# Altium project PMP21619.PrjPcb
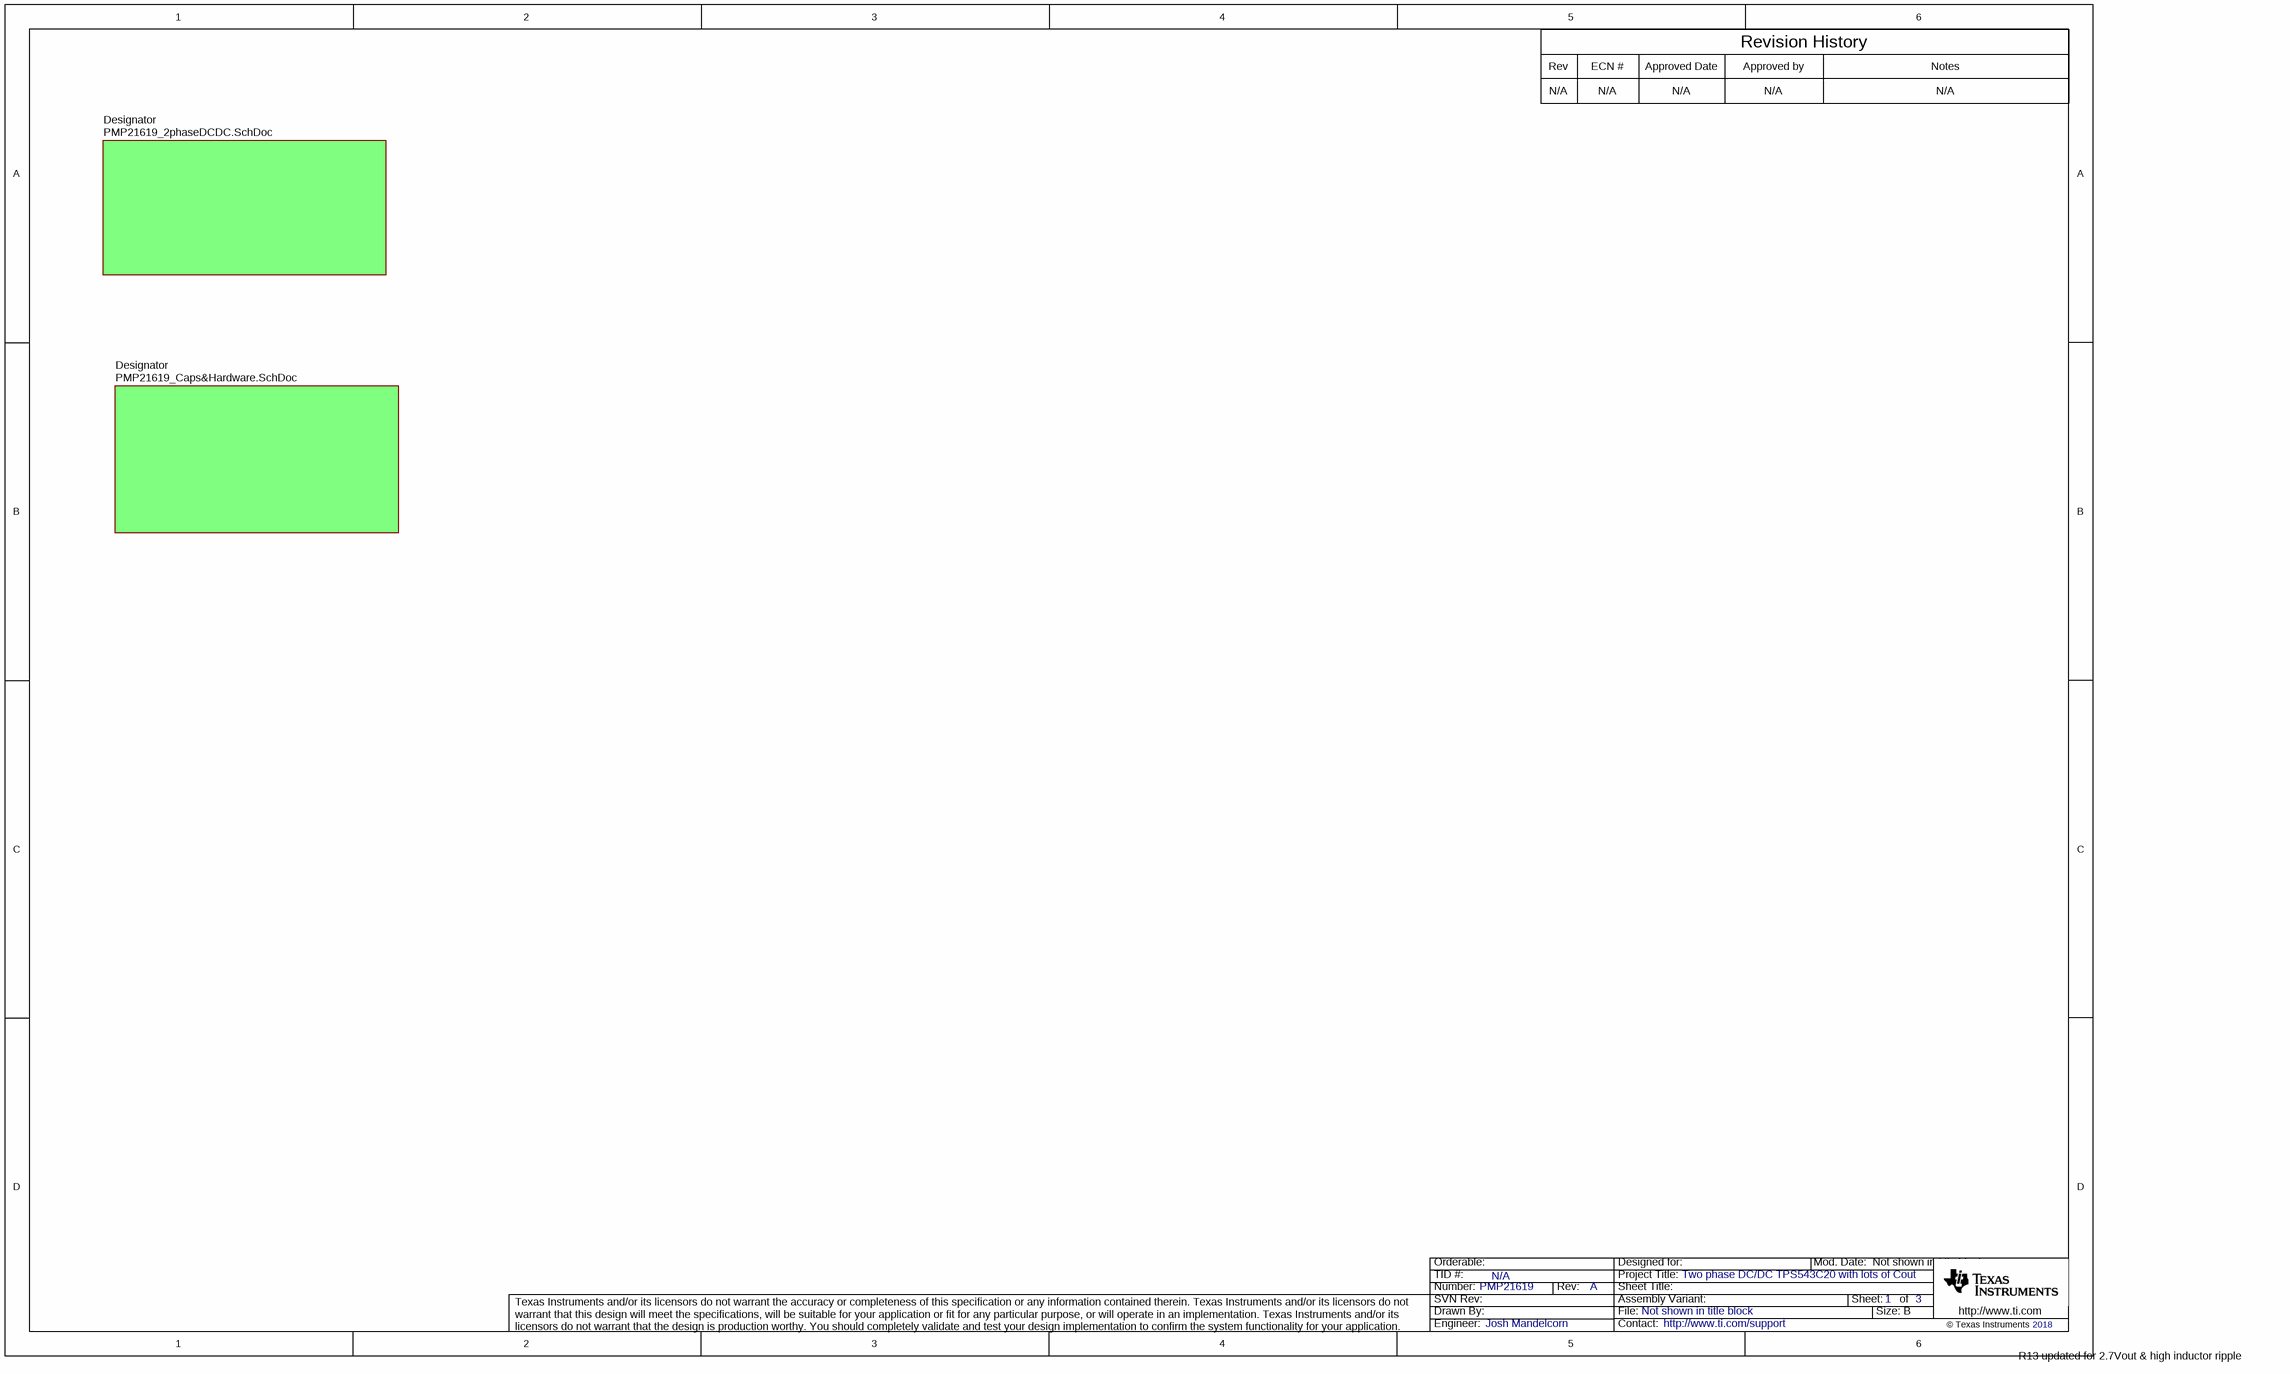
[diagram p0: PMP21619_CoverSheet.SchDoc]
CopyrightYear: 2018; PCB_Layout: Dee Lim; PCB_Rev: A; PRJ_Engineer: Josh Mandelcorn; PRJ_Number: PMP21619; PRJ_Title: Two phase DC/DC TPS543C20 with lots of Cout; SCH_Rev: A; TechSupport: http://www.ti.com/support; TID: N/A
3 sheets, 231 parts. Net scope: flat (ports and power ports of the same name join across sheets).
Board file: PMP21619_PCB.PcbDoc
Sheets:
  PMP21619_CoverSheet.SchDoc
    Designator = PMP21619_2phaseDCDC.SchDoc
    Designator = PMP21619_Caps&Hardware.SchDoc

## Sheet PMP21619_CoverSheet.SchDoc
size 431 x 279 mm; Date: Not shown in title block; ApprovedBy: Not shown in title block; CheckedBy: Not shown in title block; Author: Not shown in title block; CompanyName: Not shown in title block; Engineer: Not shown in title block; Organization: Not shown in title block; Address1: Not shown in title block; Address2: Not shown in title block; Address3: Not shown in title block; Address4: Not shown in title block; DocumentNumber: 1; Revision: Use project parameter SCH_Rev; SheetNumber: 1; SheetTotal: 3; PageSetup: Record=PageOptions¦CenterHorizontal=True¦CenterVertical=True¦PrintScale=1.00¦XCorrection=1.00¦YCorrection=1.00¦PrintKind=0¦BorderSize=5000000¦LeftOffset=0¦BottomOffset=0¦Orientation=2¦PaperLength=1000¦PaperWidth=1000¦Scale=100¦PaperSource=15¦PrintQuality=600¦MediaType=1¦DitherType=10¦PaperKind=Letter¦PrintScaleMode=1

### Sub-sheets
Designator = PMP21619_2phaseDCDC.SchDoc: no entries
Designator = PMP21619_Caps&Hardware.SchDoc: no entries

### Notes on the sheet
- Rev
- N/A
- ECN #
- Approved Date
- Approved by
- Revision History
- Notes
- R13 updated for 2.7Vout & high inductor ripple

## Sheet PMP21619_2phaseDCDC.SchDoc
size 431 x 279 mm; Date: Not shown in title block; ApprovedBy: Not shown in title block; CheckedBy: Not shown in title block; Author: Not shown in title block; CompanyName: Not shown in title block; Engineer: Not shown in title block; Organization: Not shown in title block; Address1: Not shown in title block; Address2: Not shown in title block; Address3: Not shown in title block; Address4: Not shown in title block; DocumentNumber: 1; Revision: Use project parameter SCH_Rev; SheetNumber: 2; SheetTotal: 3; PageSetup: Record=PageOptions¦CenterHorizontal=True¦CenterVertical=True¦PrintScale=1.00¦XCorrection=1.00¦YCorrection=1.00¦PrintKind=0¦BorderSize=5000000¦LeftOffset=0¦BottomOffset=0¦Orientation=2¦PaperLength=1000¦PaperWidth=1000¦Scale=100¦PaperSource=15¦PrintQuality=600¦MediaType=1¦DitherType=10¦PaperKind=Letter¦PrintScaleMode=1
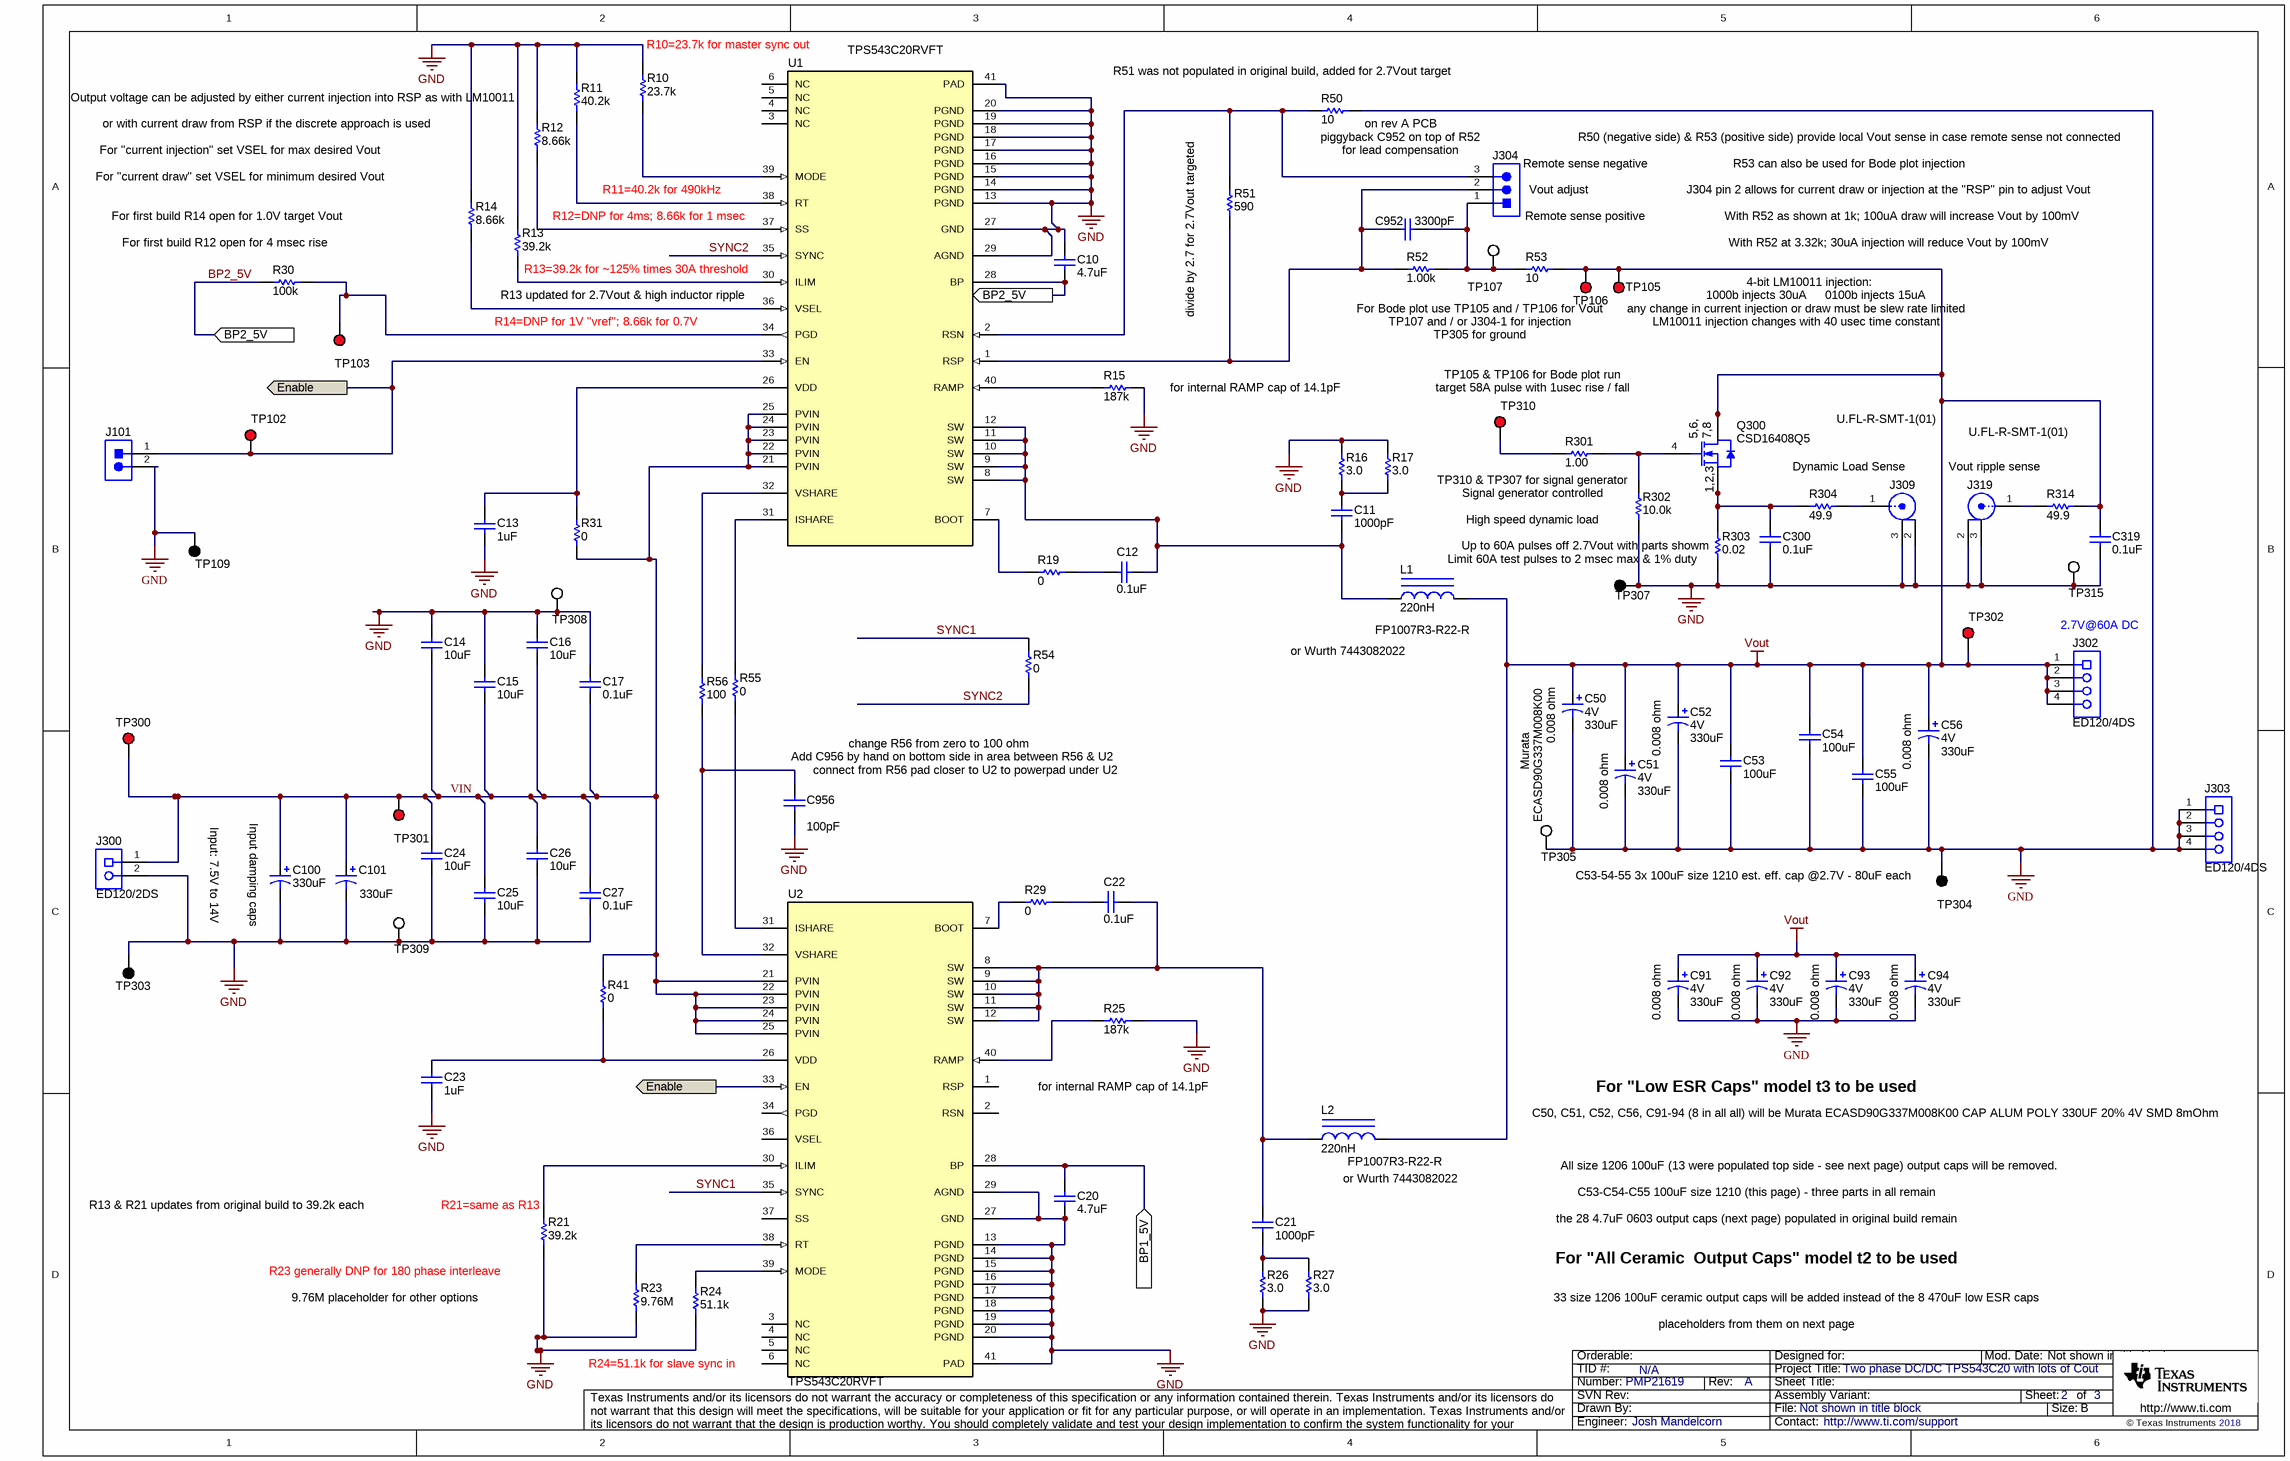
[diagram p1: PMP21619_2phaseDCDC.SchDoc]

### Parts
C10  ValueDisplayed: 4.7uF  [0805_HV]  (hidden comment: Capacitor)
C11  ValueDisplayed: 1000pF  [0603]  (hidden comment: Capacitor)
C12  ValueDisplayed: 0.1uF  [0402]  (hidden comment: Capacitor)
C13  ValueDisplayed: 1uF  [0603]  (hidden comment: Capacitor)
C14  ValueDisplayed: 10uF  [1210_280]  (hidden comment: Capacitor)
C15  ValueDisplayed: 10uF  [1210_280]  (hidden comment: Capacitor)
C16  ValueDisplayed: 10uF  [1210_280]  (hidden comment: Capacitor)
C17  ValueDisplayed: 0.1uF  [0603S]  (hidden comment: Capacitor)
C20  ValueDisplayed: 4.7uF  [0805_HV]  (hidden comment: Capacitor)
C21  ValueDisplayed: 1000pF  [0603]  (hidden comment: Capacitor)
C22  ValueDisplayed: 0.1uF  [0402]  (hidden comment: Capacitor)
C23  ValueDisplayed: 1uF  [0603]  (hidden comment: Capacitor)
C24  ValueDisplayed: 10uF  [1210_280]  (hidden comment: Capacitor)
C25  ValueDisplayed: 10uF  [1210_280]  (hidden comment: Capacitor)
C26  ValueDisplayed: 10uF  [1210_280]  (hidden comment: Capacitor)
C27  ValueDisplayed: 0.1uF  [0603S]  (hidden comment: Capacitor)
C50  ECASD90G337M008K00  Value1: 0.008 ohm  Manufacturer: Murata  VDC_V: 4V  ValueDisplayed: 330uF  [CAPSMT_62_H70]
C51  Value1: 0.008 ohm  VDC_V: 4V  ValueDisplayed: 330uF  [CAPSMT_62_H70]  (hidden comment: ECASD90G337M008K00)
C52  Value1: 0.008 ohm  VDC_V: 4V  ValueDisplayed: 330uF  [CAPSMT_62_H70]  (hidden comment: ECASD90G337M008K00)
C53  ValueDisplayed: 100uF  [1210_280]  (hidden comment: Capacitor)
C54  ValueDisplayed: 100uF  [1210_280]  (hidden comment: Capacitor)
C55  ValueDisplayed: 100uF  [1210_280]  (hidden comment: Capacitor)
C56  Value1: 0.008 ohm  VDC_V: 4V  ValueDisplayed: 330uF  [CAPSMT_62_H70]  (hidden comment: ECASD90G337M008K00)
C91  Value1: 0.008 ohm  VDC_V: 4V  ValueDisplayed: 330uF  [CAPSMT_62_H70]  (hidden comment: ECASD90G337M008K00)
C92  Value1: 0.008 ohm  VDC_V: 4V  ValueDisplayed: 330uF  [CAPSMT_62_H70]  (hidden comment: ECASD90G337M008K00)
C93  Value1: 0.008 ohm  VDC_V: 4V  ValueDisplayed: 330uF  [CAPSMT_62_H70]  (hidden comment: ECASD90G337M008K00)
C94  Value1: 0.008 ohm  VDC_V: 4V  ValueDisplayed: 330uF  [CAPSMT_62_H70]  (hidden comment: ECASD90G337M008K00)
C100  value 330uF  [SM_RADIAL_G]  (hidden comment: Cap_Polarized)
C101  value 330uF  [SM_RADIAL_G]  (hidden comment: Cap_Polarized)
C300  ValueDisplayed: 0.1uF  [0603]  (hidden comment: Capacitor)
C319  ValueDisplayed: 0.1uF  [0603]  (hidden comment: Capacitor)
C952  ValueDisplayed: 3300pF  [0402]  (hidden comment: GCM155R71H332KA37D)
C956  ValueDisplayed: 100pF  [0402]  (hidden comment: 0402YC101KAT2A)
J101  Header_2x1  [Mill-Max_800-10-002-10-001000]  (value not drawn)
J300  ED120/2DS  [On-Shore_ED120_2DS]
J302  ED120/4DS  [On-Shore_ED120_4DS]
J303  ED120/4DS  [On-Shore_ED120_4DS]
J304  800-10-003-10-001000  [Mill-Max_800-10-003-10-001000]  (value not drawn)
J309  U.FL-R-SMT-1(01)  [CONN_UFL-R-SMT-1]
J319  U.FL-R-SMT-1(01)  [CONN_UFL-R-SMT-1]
L1  FP1007R3-R22-R  ValueDisplayed: 220nH  [IND_FP1007R3]
L2  FP1007R3-R22-R  ValueDisplayed: 220nH  [IND_FP1007R3]
Q300  CSD16408Q5  [DQH0008A]
R10  ValueDisplayed: 23.7k  [0402]  (hidden comment: Resistor)
R11  ValueDisplayed: 40.2k  [0402]  (hidden comment: Resistor)
R12  ValueDisplayed: 8.66k  [0402]  (hidden comment: Resistor)
R13  ValueDisplayed: 39.2k  [0402]  (hidden comment: CRCW040239K2FKED)
R14  ValueDisplayed: 8.66k  [0402]  (hidden comment: Resistor)
R15  ValueDisplayed: 187k  [0402]  (hidden comment: Resistor)
R16  value 3.0  [0805_HV]  (hidden comment: Resistor)
R17  value 3.0  [0805_HV]  (hidden comment: Resistor)
R19  ValueDisplayed: 0  [0402]  (hidden comment: Resistor)
R21  ValueDisplayed: 39.2k  [0402]  (hidden comment: CRCW040239K2FKED)
R23  ValueDisplayed: 9.76M  [0402]  (hidden comment: CRCW04029M76FKED)
R24  ValueDisplayed: 51.1k  [0402]  (hidden comment: Resistor)
R25  ValueDisplayed: 187k  [0402]  (hidden comment: Resistor)
R26  value 3.0  [0805_HV]  (hidden comment: Resistor)
R27  value 3.0  [0805_HV]  (hidden comment: Resistor)
R29  ValueDisplayed: 0  [0402]  (hidden comment: Resistor)
R30  ValueDisplayed: 100k  [0402]  (hidden comment: Resistor)
R31  ValueDisplayed: 0  [0402]  (hidden comment: Resistor)
R41  ValueDisplayed: 0  [0402]  (hidden comment: Resistor)
R50  ValueDisplayed: 10  [0402]  (hidden comment: Resistor)
R51  ValueDisplayed: 590  [0402]  (hidden comment: CRCW0402590RFKED)
R52  ValueDisplayed: 1.00k  [0402]  (hidden comment: Resistor)
R53  ValueDisplayed: 10  [0402]  (hidden comment: Resistor)
R54  ValueDisplayed: 0  [0402]  (hidden comment: Resistor)
R55  ValueDisplayed: 0  [0402]  (hidden comment: Resistor)
R56  ValueDisplayed: 100  [0402]  (hidden comment: ERJ-2RKF1000X)
R301  ValueDisplayed: 1.00  [0603]  (hidden comment: Resistor)
R302  ValueDisplayed: 10.0k  [0603]  (hidden comment: Resistor)
R303  ValueDisplayed: 0.02  [2512]  (hidden comment: Resistor)
R304  ValueDisplayed: 49.9  [0402]  (hidden comment: Resistor)
R314  ValueDisplayed: 49.9  [0402]  (hidden comment: Resistor)
TP102  5000  [Keystone5000]  (value not drawn)
TP103  5000  [Keystone5000]  (value not drawn)
TP105  5000  [Keystone5000]  (value not drawn)
TP106  5000  [Keystone5000]  (value not drawn)
TP107  5002  [Keystone5002]  (value not drawn)
TP109  5001  [Keystone5001]  (value not drawn)
TP300  5000  [Keystone5000]  (value not drawn)
TP301  5000  [Keystone5000]  (value not drawn)
TP302  5000  [Keystone5000]  (value not drawn)
TP303  5001  [Keystone5001]  (value not drawn)
TP304  5001  [Keystone5001]  (value not drawn)
TP305  5016  [Testpoint_Keystone_Compact]  (value not drawn)
TP307  5001  [Keystone5001]  (value not drawn)
TP308  5016  [Testpoint_Keystone_Compact]  (value not drawn)
TP309  5016  [Testpoint_Keystone_Compact]  (value not drawn)
TP310  5000  [Keystone5000]  (value not drawn)
TP315  5016  [Testpoint_Keystone_Compact]  (value not drawn)
U1  PartNumber: TPS543C20RVFT  [RVF0040A]
U2  TPS543C20RVFT  [RVF0040A]

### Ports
BP1_5V, BP2_5V, Enable

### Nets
GND: C10.1 C13.2 C14.1 C15.1 C16.1 C17.1 C20.2 C23.2 C24.2 C25.2 C26.2 C27.2 C50.2(-) C51.2(-) C52.2(-) C53.2 C54.2 C55.2 C56.2(-) C91.2(-) C92.2(-) C93.2(-) C94.2(-) C100.2(-) C101.2(-) C300.2 C319.2 C956.2 J101.2 J300.2 J303.1 J303.2 J303.3 J303.4 J309.2 J309.3 J319.2 J319.3 R10.1 R11.1 R12.1 R13.2 R14.2 R15.2 R16.1 R17.1 R21.1 R23.1 R24.1 R25.2 R26.1 R27.2 R50.1 R302.1 R303.1 TP109.1 TP303.1 TP304.1 TP305.1 TP307.1 TP308.1 TP309.1 TP315.1 U1.13(PGND) U1.14(PGND) U1.15(PGND) U1.16(PGND) U1.17(PGND) U1.18(PGND) U1.19(PGND) U1.20(PGND) U1.27(GND) U1.29(AGND) U1.41(PAD) U2.13(PGND) U2.14(PGND) U2.15(PGND) U2.16(PGND) U2.17(PGND) U2.18(PGND) U2.19(PGND) U2.20(PGND) U2.27(GND) U2.29(AGND) U2.41(PAD)
Vout: C50.1(+) C51.1(+) C52.1(+) C53.1 C54.1 C55.1 C56.1(+) C91.1(+) C92.1(+) C93.1(+) C94.1(+) C319.1 J302.1 J302.2 J302.3 J302.4 L1.2 L2.2 Q300.5(D) Q300.6(D) Q300.7(D) Q300.8(D) Q300.9(D) R53.1 R314.2 TP105.1 TP106.1 TP302.1
BP1_5V: C20.1 U2.28(BP) ; port BP1_5V
BP2_5V: C10.2 R30.1 U1.28(BP) ; port BP2_5V
Enable: J101.1 TP102.1 U1.33(EN) U2.33(EN) ; port Enable
SYNC1: R54.2 U2.35(SYNC)
SYNC2: R54.1 U1.35(SYNC)
VIN: C14.2 C15.2 C16.2 C17.2 C24.1 C25.1 C26.1 C27.1 C100.1(+) C101.1(+) J300.1 R31.1 R41.2 TP300.1 TP301.1 U1.21(PVIN) U1.22(PVIN) U1.23(PVIN) U1.24(PVIN) U1.25(PVIN) U2.21(PVIN) U2.22(PVIN) U2.23(PVIN) U2.24(PVIN) U2.25(PVIN)
NetC11_1: C11.1 C12.2 L1.1 U1.8(SW) U1.9(SW) U1.10(SW) U1.11(SW) U1.12(SW)
NetC11_2: C11.2 R16.2 R17.2
NetC12_1: C12.1 R19.1
NetC13_1: C13.1 R31.2 U1.26(VDD)
NetC21_1: C21.1 C22.2 L2.1 U2.8(SW) U2.9(SW) U2.10(SW) U2.11(SW) U2.12(SW)
NetC21_2: C21.2 R26.2 R27.1
NetC22_1: C22.1 R29.1
NetC23_1: C23.1 R41.1 U2.26(VDD)
NetC300_1: C300.1 Q300.1(S) Q300.2(S) Q300.3(S) R303.2 R304.1
NetC952_1: C952.1 J304.2 R51.1 R52.2 U1.1(RSP)
NetC952_2: C952.2 J304.1 R52.1 R53.2 TP107.1
NetC956_1: C956.1 R56.1 U2.32(VSHARE)
NetJ304_3: J304.3 R50.2 R51.2 U1.2(RSN)
NetJ309_1: J309.1 R304.2
NetJ319_1: J319.1 R314.1
NetQ300_4: Q300.4(G) R301.1 R302.2
NetR10_2: R10.2 U1.39(MODE)
NetR11_2: R11.2 U1.38(RT)
NetR12_2: R12.2 U1.37(SS)
NetR13_1: R13.1 U1.30(ILIM)
NetR14_1: R14.1 U1.36(VSEL)
NetR15_1: R15.1 U1.40(RAMP)
NetR19_2: R19.2 U1.7(BOOT)
NetR21_2: R21.2 U2.30(ILIM)
NetR23_2: R23.2 U2.38(RT)
NetR24_2: R24.2 U2.39(MODE)
NetR25_1: R25.1 U2.40(RAMP)
NetR29_2: R29.2 U2.7(BOOT)
NetR30_2: R30.2 TP103.1 U1.34(PGD)
NetR55_1: R55.1 U2.31(ISHARE)
NetR55_2: R55.2 U1.31(ISHARE)
NetR56_2: R56.2 U1.32(VSHARE)
NetR301_2: R301.2 TP310.1

Not connected (* = marked no-connect by the designer): U1 3(NC) 4(NC) 5(NC) 6(NC); U2 1(RSP) 2(RSN) 3(NC) 4(NC) 5(NC) 6(NC) 34(PGD) 36(VSEL) 37(SS)

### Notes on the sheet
- (near R12) Output voltage can be adjusted by either current injection into RSP as with LM10011
- R10=23.7k for master sync out
- (near R50) R51 was not populated in original build, added for 2.7Vout target
- For "current injection" set VSEL for max desired Vout
- or with current draw from RSP if the discrete approach is used
- (near R50) on rev A PCB
- (near R50) piggyback C952 on top of R52
- for lead compensation
- (near J304) Remote sense negative
- R50 (negative side) & R53 (positive side) provide local Vout sense in case remote sense not connected
- R53 can also be used for Bode plot injection
- For first build R14 open for 1.0V target Vout
- For "current draw" set VSEL for minimum desired Vout
- R12=DNP for 4ms; 8.66k for 1 msec
- R11=40.2k for 490kHz
- (near R51) divide by 2.7 for 2.7Vout targeted
- (near J304) Vout adjust
- Remote sense positive
- J304 pin 2 allows for current draw or injection at the "RSP" pin to adjust Vout
- With R52 as shown at 1k; 100uA draw will increase Vout by 100mV
- (near R30) For first build R12 open for 4 msec rise
- R13 updated for 2.7Vout & high inductor ripple
- (near R13) R13=39.2k for
  25% times 30A threshold
- 1000b injects 30uA
- 4-bit LM10011 injection:
- 0100b injects 15uA
- With R52 at 3.32k; 30uA injection will reduce Vout by 100mV
- R14=DNP for 1V "vref"; 8.66k for 0.7V
- For Bode plot use TP105 and / TP106 for Vout
- TP107 and / or J304-1 for injection
- TP305 for ground
- any change in current injection or draw must be slew rate limited
- (near TP105) LM10011 injection changes with 40 usec time constant
- (near R15) for internal RAMP cap of 14.1pF
- TP105 & TP106 for Bode plot run
- (near TP310) target 58A pulse with 1usec rise / fall
- Signal generator controlled
- (near R302) TP310 & TP307 for signal generator
- Dynamic Load Sense
- Vout ripple sense
- High speed dynamic load
- Limit 60A test pulses to 2 msec max & 1% duty
- (near R303) Up to 60A pulses off 2.7Vout with parts showm
- 2.7V@60A DC
- (near L1) or Wurth 7443082022
- change R56 from zero to 100 ohm
- (near C956) Add C956 by hand on bottom side in area between R56 & U2
- (near C956) connect from R56 pad closer to U2 to powerpad under U2
- Input: 7.5V to 14V
- (near C100) Input damping caps
- (near TP304) C53-54-55 3x 100uF size 1210 est. eff. cap @2.7V - 80uF each
- for internal RAMP cap of 14.1pF
- For "Low ESR Caps" model t3 to be used
- C50, C51, C52, C56, C91-94 (8 in all all) will be Murata ECASD90G337M008K00 CAP ALUM POLY 330UF 20% 4V SMD 8mOhm
- R13 & R21 updates from original build to 39.2k each
- (near R21) R21=same as R13
- (near L2) or Wurth 7443082022
- C53-C54-C55 100uF size 1210 (this page) - three parts in all remain
- the 28 4.7uF 0603 output caps (next page) populated in original build remain
- All size 1206 100uF (13 were populated top side - see next page) output caps will be removed.
- (near R21) R23 generally DNP for 180 phase interleave
- For "All Ceramic  Output Caps" model t2 to be used
- 9.76M placeholder for other options
- placeholders from them on next page
- 33 size 1206 100uF ceramic output caps will be added instead of the 8 470uF low ESR caps
- R24=51.1k for slave sync in

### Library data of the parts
C10 C20 = CMP-0007870-2: CAP, CERM, 4.7 uF, 25 V, +/- 10%, X7R, 0805; PartNumber: C2012X7R1E475K125AB; Manufacturer: TDK; Polarized: N; Value: 4.7uF; U/M: EA; Cap_F: 4.7µF; Value1: Unknown; VDC_V: 25V; TaMin_C: -55°C; TaMax_C: 125°C; Cap_Case: 0805; AEC Category: Q200; SizeArea_mm2: 2.5; SizeAreaWB_mm2: 6.75; SizeX_mm: 2; SizeY_mm: 1.25; SizeZ_mm: 1.45
C11 C21 = CMP-0006764-4: CAP, CERM, 1000 pF, 50 V, +/- 10%, C0G/NP0, 0603; PartNumber: 06035A102KAT2A; Manufacturer: AVX; Polarized: N; Value: 1000pF; U/M: EA; Cap_F: 1nF; ESR_ohm: 0.048; Value1: 0.048 ohm; VDC_V: 50V; TaMin_C: -55°C; TaMax_C: 125°C; AEC Category: Q200; SizeArea_mm2: 1.28; SizeAreaWB_mm2: 4.68; SizeX_mm: 1.6; SizeY_mm: 0.8; SizeZ_mm: 1
C12 C22 = CMP-0006720-2: CAP, CERM, 0.1 uF, 25 V, +/- 20%, X7R, 0402; PartNumber: TMK105B7104MV-FR; Manufacturer: Taiyo Yuden; Polarized: N; Value: 0.1uF; U/M: EA; Cap_F: 100nF; Value1: Unknown; VDC_V: 25V; TaMin_C: -55°C; TaMax_C: 125°C; AEC Category: Q200; SizeArea_mm2: 0.5; SizeAreaWB_mm2: 3; SizeX_mm: 1; SizeZ_mm: 0.6
C13 C23 = CMP-0007040-4: CAP, CERM, 1 uF, 25 V, +/- 10%, X7R, 0603; PartNumber: C1608X7R1E105K080AB; Manufacturer: TDK; Polarized: N; Value: 1uF; U/M: EA; Cap_F: 1µF; Value1: Unknown; VDC_V: 25V; TaMin_C: -55°C; TaMax_C: 125°C; AEC Category: Q200; SizeArea_mm2: 1.28; SizeAreaWB_mm2: 4.68; SizeX_mm: 1.6; SizeY_mm: 0.8; SizeZ_mm: 1
C14-C16 C24-C26 = CMP-0009117-1: CAP, CERM, 10 uF, 25 V, +/- 20%, X7R, 1210; PartNumber: C3225X7R1E106M250AC; Manufacturer: TDK; Polarized: N; Value: 10uF; U/M: EA; Cap_F: 10µF; Value1: Unknown; VDC_V: 25V; TaMin_C: -55°C; TaMax_C: 125°C; Cap_Case: 1210; SizeArea_mm2: 8; SizeAreaWB_mm2: 14.7; SizeX_mm: 3.2; SizeY_mm: 2.5; SizeZ_mm: 2.8; AEC Category: Q200
C17 C27 = CMP-0007404-4: CAP, CERM, 0.1 uF, 25 V, +/- 10%, X7R, 0603; PartNumber: GRM188R71E104KA01D; Manufacturer: MuRata; Polarized: N; Value: 0.1uF; U/M: EA; Cap_F: 100nF; Value1: Unknown; VDC_V: 25V; TaMin_C: -55°C; TaMax_C: 125°C; Cap_Case: 0603; AEC Category: Q200; SizeArea_mm2: 1.28; SizeAreaWB_mm2: 4.68; SizeX_mm: 1.6; SizeY_mm: 0.8; SizeZ_mm: 1
C50 = CMP-0010591-1: CAP, AL, 330 uF, 4 V, +/- 20%, 0.008 ohm, SMD; TaMin_C: -55°C; ESR_ohm: 0.014; Polarized: Y; SizeAreaWB_mm2: 110.25; U/M: EA; Value: 330uF; TaMax_C: 105°C; SizeZ_mm: 7; SizeX_mm: 8.5; Cap_Case: H70; SizeArea_mm2: 72.25; CompType: Capacitor; Cap_F: 470µF; IRMS_A: 3.95A; AEC Category: Q200
C51 C52 C56 C91-C94 = CMP-0010591-1: CAP, AL, 330 uF, 4 V, +/- 20%, 0.008 ohm, SMD; Manufacturer: Murata; TaMin_C: -55°C; ESR_ohm: 0.014; Polarized: Y; SizeAreaWB_mm2: 110.25; U/M: EA; Value: 330uF; TaMax_C: 105°C; SizeZ_mm: 7; SizeX_mm: 8.5; Cap_Case: H70; SizeArea_mm2: 72.25; CompType: Capacitor; Cap_F: 470µF; IRMS_A: 3.95A; AEC Category: Q200
C53-C55 = CMP-0009110-2: CAP, CERM, 100 uF, 6.3 V, +/- 20%, X6S, 1210; PartNumber: C3225X6S0J107M250AC; Manufacturer: TDK; Polarized: N; Value: 100uF; U/M: EA; Cap_F: 100µF; ESR_ohm: 5.496m; Value1: 0.005496 ohm; VDC_V: 6.3V; IRMS_A: 3.13651A; TaMin_C: -55°C; TaMax_C: 105°C; AEC Category: Q200; SizeArea_mm2: 8; SizeAreaWB_mm2: 14.7; SizeX_mm: 3.2; SizeY_mm: 2.5; SizeZ_mm: 2.8
C100 C101 = CMP-0010657-1: CAP, AL, 330 uF, 25 V, +/- 20%, 0.15 ohm, SMD; PartNumber: EEE-FC1E331P; Manufacturer: Panasonic; Polarized: Y; CompType: Capacitor; U/M: EA; Cap_F: 330µF; VDC_V: 25V; ESR_ohm: 1.5d; IRMS_A: 6.7dA; TaMin_C: -40°C; TaMax_C: 105°C; Cap_Case: G; AEC Category: Q200; SizeArea_mm2: 123.6; SizeAreaWB_mm2: 172.2; SizeX_mm: 12; SizeY_mm: 10.3; SizeZ_mm: 10.2
C300 C319 = CMP-0006981-4: CAP, CERM, 0.1 uF, 10 V, +/- 10%, X7R, 0603; PartNumber: C0603X104K8RACTU; Manufacturer: Kemet; Polarized: N; Value: 0.1uF; U/M: EA; Cap_F: 100nF; Value1: Unknown; VDC_V: 10V; TaMin_C: -55°C; TaMax_C: 125°C; SizeArea_mm2: 1.28; SizeAreaWB_mm2: 4.68; SizeX_mm: 1.6; SizeY_mm: 0.8; SizeZ_mm: 1; AEC Category: Q200
C952 = CMP-0006359-2: CAP, CERM, 3300 pF, 50 V, +/- 10%, X7R, AEC-Q200 Grade 1, 0402; Manufacturer: MuRata; TaMin_C: -55°C; Polarized: N; SizeAreaWB_mm2: 3; Value1: Unknown; U/M: EA; Value: 3300pF; TaMax_C: 125°C; SizeZ_mm: 0.6; SizeX_mm: 1; SizeY_mm: 0.5; Value2: 50V; CompType: Capacitor; AEC Qualified: Y; Cap_F: 3.3nF; AEC Category: Q200
C956 = CMP-0006200-2: CAP, CERM, 100 pF, 16 V, +/- 10%, X7R, 0402; Manufacturer: AVX; TaMin_C: -55°C; Polarized: N; SizeAreaWB_mm2: 3; Value1: Unknown; U/M: EA; Value: 100pF; TaMax_C: 125°C; SizeZ_mm: 0.6; SizeX_mm: 1; SizeY_mm: 0.5; Value2: 16V; CompType: Capacitor; AEC Category: Q200
J101 = CMP-0055085-1: Header, 100mil, 2x1, TH; PartNumber: 800-10-002-10-001000; Manufacturer: Mill-Max; CNHeader: TRUE; CT: FALSE; Green_Lifecycle: Active; Green_REACh: Passed
J300 = CMP-0074910-1: Terminal Block, 5.08 mm, 2x1, Brass, TH; Manufacturer: On-Shore Technology; Cert_VDE: Y; CNHeader: False; Current_A: 15A; Green_Lifecycle: Not Set; Shrouded: N; Gender: Female; Green_REACh: Incomplete; Voltage_V: 300V; Row_Count: 1; Pitch_mm: 5.08; CT: True
J302 J303 = CMP-0074939-1: Terminal Block, 5.08 mm, 4x1, Brass, TH; Manufacturer: On-Shore Technology; Cert_VDE: Y; CNHeader: False; Current_A: 15A; Green_Lifecycle: Not Set; Shrouded: N; Gender: Female; Green_REACh: Incomplete; Voltage_V: 300V; Row_Count: 1; Pitch_mm: 5.08; CT: True
J304 = CMP-0055086-1: Header, 100mil, 3x1, TH; Manufacturer: Mill-Max; CNHeader: TRUE; Green_Lifecycle: Active; Green_REACh: Passed; CT: FALSE
J309 J319 = CMP-0075320-1: Receptacle, Ultra Miniature Coaxial, Male Pin, 50 ohm, SMT; Manufacturer: Hirose Electric Co. Ltd.; CNHeader: False; Gender: Female; ContactFinish: Gold
L1 L2 = CMP-0058392-1: Inductor, Wirewound, Ferrite, 220 nH, 50 A, 0.00029 ohm, SMD; Manufacturer: Coiltronics; Isat: 50A @ 20% inductance drop; Irms: 61A @ 40C rise; Green_Lifecycle: Not Set; SizeAreaWB_mm2: 124; DCR_ohm: 290µ; Green_REACh: Incomplete; Value: 220nH; Imax_A: 50A; SizeZ_mm: 7.5; SizeX_mm: 8; SizeY_mm: 10.4; SizeArea_mm2: 83.2; AEC Category: Q200
Q300 = CMP-0000264-1: MOSFET, N-CH, 25 V, 113 A, DQH0008A (VSON-CLIP-8); Manufacturer: Texas Instruments; Alternate Manufacturer: None; U/M: EA; ChType: N; Value: 25V; Value1: 0.005; Rdson45_ohm: 5.4m; Value2: 6.7 nC; QgTyp_nC: 6.7; Vgs_V: 16V; IdsMax_A: 113A; SizeAreaWB_mm2: 56; SizeArea_mm2: 30; SizeX_mm: 6; SizeY_mm: 5; SizeZ_mm: 1.05; AEC Category: Q101
R10 = CMP-0026683-1: RES, 23.7 k, 1%, 0.1 W, AEC-Q200 Grade 0, 0402; PartNumber: ERJ-2RKF2372X; Manufacturer: Panasonic; Value: 23.7k; Value_Code: 23k7; Power_W: 100mW; Value2: 0.1W; VDC_V: 50V; TempCo: 100 ppm/C; EIA_Code: E96; U/M: EA; AEC Category: Q200; AEC Qualified: Y; AEC Grade: 0; SizeArea_mm2: 0.5; SizeX_mm: 1; SizeZ_mm: 0.6
R11 = CMP-0026367-2: RES, 40.2 k, 1%, 0.063 W, AEC-Q200 Grade 0, 0402; PartNumber: CRCW040240K2FKED; Manufacturer: Vishay-Dale; Value: 40.2k; Value_Code: 40k2; Power_W: 63mW; Value2: 0.063W; VDC_V: 50V; TempCo: 100 ppm/C; EIA_Code: E96; AEC Category: Q200; AEC Qualified: Y; AEC Grade: 0; SizeArea_mm2: 0.5; SizeX_mm: 1; SizeZ_mm: 0.6
R12 R14 = CMP-0026591-2: RES, 8.66 k, 1%, 0.063 W, AEC-Q200 Grade 0, 0402; PartNumber: CRCW04028K66FKED; Manufacturer: Vishay-Dale; Value: 8.66k; Value_Code: 8k66; Power_W: 63mW; Value2: 0.063W; VDC_V: 50V; TempCo: 100 ppm/C; EIA_Code: E96; AEC Category: Q200; AEC Qualified: Y; AEC Grade: 0; SizeArea_mm2: 0.5; SizeX_mm: 1; SizeZ_mm: 0.6
R13 R21 = CMP-0026327-2: RES, 39.2 k, 1%, 0.063 W, AEC-Q200 Grade 0, 0402; Manufacturer: Vishay-Dale; Power_W: 63mW; TempCo: 100 ppm/C; Value_Code: 39k2; Value: 39.2k; EIA_Code: E96; SizeX_mm: 1; SizeY_mm: 0.5; SizeZ_mm: 0.6; Value2: 0.063W; AEC Qualified: Y; VDC_V: 50V; AEC Category: Q200; AEC Grade: 0
R15 R25 = CMP-0026056-3: RES, 187 k, 1%, 0.063 W, AEC-Q200 Grade 0, 0402; PartNumber: CRCW0402187KFKED; Manufacturer: Vishay-Dale; Value: 187k; Power_W: 63mW; Value2: 0.063W; VDC_V: 50V; TempCo: 100 ppm/C; EIA_Code: E96; AEC Category: Q200; AEC Qualified: Y; AEC Grade: 0; SizeArea_mm2: 0.5; SizeX_mm: 1; SizeZ_mm: 0.6
R16 R17 R26 R27 = CMP-0020820-2: RES, 3.0, 5%, 0.125 W, 0805; PartNumber: RC0805JR-073RL; Manufacturer: Yageo America; Res_ohm: 3; Value_Code: 3R00; Power_W: 125mW; Value2: 0.125W; VDC_V: 150V; TempCo: 200 ppm/C; EIA_Code: E24; U/M: EA; AEC Category: Q200; SizeArea_mm2: 2.5; SizeX_mm: 2; SizeY_mm: 1.25; SizeZ_mm: 1.45
R19 R29 R31 R41 R54 = CMP-0026822-3: RES, 0, 5%, 0.063 W, AEC-Q200 Grade 0, 0402; PartNumber: CRCW04020000Z0ED; Manufacturer: Vishay-Dale; Value: 0; Value_Code: 0000; Power_W: 63mW; Value2: 0.063W; VDC_V: 50V; TempCo: 200 ppm/C; EIA_Code: E24; AEC Category: Q200; AEC Qualified: Y; SizeArea_mm2: 0.5; SizeX_mm: 1; SizeZ_mm: 0.6
R23 = CMP-0026626-3: RES, 9.76 M, 1%, 0.063 W, AEC-Q200 Grade 0, 0402; Manufacturer: Vishay-Dale; Power_W: 63mW; TempCo: 100 ppm/C; Value_Code: 9M76; Value: 9.76Meg; EIA_Code: E96; SizeX_mm: 1; SizeY_mm: 0.5; SizeZ_mm: 0.6; Value2: 0.063W; CompType: Resistor; AEC Qualified: Y; VDC_V: 50V; AEC Category: Q200; AEC Grade: 0
R24 = CMP-0026437-2: RES, 51.1 k, 1%, 0.063 W, AEC-Q200 Grade 0, 0402; PartNumber: CRCW040251K1FKED; Manufacturer: Vishay-Dale; Value: 51.1k; Value_Code: 51k1; Power_W: 63mW; Value2: 0.063W; VDC_V: 50V; TempCo: 100 ppm/C; EIA_Code: E96; AEC Category: Q200; AEC Qualified: Y; AEC Grade: 0; SizeArea_mm2: 0.5; SizeX_mm: 1; SizeZ_mm: 0.6
R30 = CMP-0026823-3: RES, 100 k, 5%, 0.063 W, AEC-Q200 Grade 0, 0402; PartNumber: CRCW0402100KJNED; Manufacturer: Vishay-Dale; Value: 100k; Power_W: 63mW; Value2: 0.063W; VDC_V: 50V; TempCo: 200 ppm/C; EIA_Code: E24; AEC Category: Q200; AEC Qualified: Y; AEC Grade: 0; SizeArea_mm2: 0.5; SizeX_mm: 1; SizeZ_mm: 0.6
R50 R53 = CMP-0026827-3: RES, 10, 5%, 0.063 W, AEC-Q200 Grade 0, 0402; PartNumber: CRCW040210R0JNED; Manufacturer: Vishay-Dale; Value: 10; Value_Code: 10R0; Power_W: 63mW; Value2: 0.063W; VDC_V: 50V; TempCo: 200 ppm/C; EIA_Code: E24; AEC Category: Q200; AEC Qualified: Y; AEC Grade: 0; SizeArea_mm2: 0.5; SizeX_mm: 1; SizeZ_mm: 0.6
R51 = CMP-0026460-2: RES, 590, 1%, 0.063 W, AEC-Q200 Grade 0, 0402; Manufacturer: Vishay-Dale; Power_W: 63mW; TempCo: 100 ppm/C; Value_Code: 590R; Value: 590; EIA_Code: E96; SizeX_mm: 1; SizeY_mm: 0.5; SizeZ_mm: 0.6; Value2: 0.063W; AEC Qualified: Y; VDC_V: 50V; AEC Category: Q200; AEC Grade: 0
R52 = CMP-0026071-3: RES, 1.00 k, 1%, 0.063 W, AEC-Q200 Grade 0, 0402; PartNumber: CRCW04021K00FKED; Manufacturer: Vishay-Dale; Value: 1.00k; Res_ohm: 1k; Value_Code: 1k00; Power_W: 63mW; Value2: 0.063W; VDC_V: 50V; TempCo: 100 ppm/C; EIA_Code: E96; AEC Category: Q200; AEC Qualified: Y; AEC Grade: 0; SizeArea_mm2: 0.5; SizeX_mm: 1; SizeZ_mm: 0.6
R55 = CMP-0026822-3: RES, 0, 5%, 0.063 W, AEC-Q200 Grade 0, 0402; PartNumber: CRCW04020000Z0ED; Manufacturer: Vishay-Dale; Value: 0; Value_Code: 0000; Power_W: 63mW; Value2: 0.063W; VDC_V: 50V; TempCo: 200 ppm/C; EIA_Code: E24; SizeArea_mm2: 0.5; SizeX_mm: 1; SizeZ_mm: 0.6; AEC Category: Q200; AEC Qualified: Y
R56 = CMP-0026656-1: RES, 100, 1%, 0.1 W, 0402; Manufacturer: Panasonic; Power_W: 100mW; TempCo: 100 ppm/C; Value_Code: 100R; U/M: EA; Value: 100; EIA_Code: E96; SizeX_mm: 1; SizeY_mm: 0.5; SizeZ_mm: 0.6; Value2: 0.1W; VDC_V: 50V; AEC Category: Q200
R301 = CMP-0022170-4: RES, 1.00, 1%, 0.1 W, AEC-Q200 Grade 0, 0603; PartNumber: CRCW06031R00FKEA; Manufacturer: Vishay-Dale; Value: 1.00; Res_ohm: 1; Value_Code: 1R00; Power_W: 100mW; Value2: 0.1W; VDC_V: 75V; TempCo: 100 ppm/C; EIA_Code: E96; AEC Category: Q200; AEC Qualified: Y; AEC Grade: 0; SizeArea_mm2: 1.28; SizeX_mm: 1.6; SizeY_mm: 0.8
R302 = CMP-0023341-3: RES, 10.0 k, 1%, 0.1 W, AEC-Q200 Grade 0, 0603; PartNumber: RMCF0603FT10K0; Manufacturer: Stackpole Electronics Inc; Value: 10.0k; Res_ohm: 10k; Value_Code: 10k0; Power_W: 100mW; Value2: 0.1W; VDC_V: 75V; TempCo: 100 ppm/C; SizeArea_mm2: 1.28; SizeX_mm: 1.6; SizeY_mm: 0.8; SizeZ_mm: 1; EIA_Code: E96; U/M: EA; AEC Category: Q200; AEC Qualified: Y; AEC Grade: 0
R303 = CMP-0015420-2: RES, 0.02, 1%, 3 W, 2512; PartNumber: CRA2512-FZ-R020ELF; Manufacturer: Bourns; Value: 0.02; Value_Code: R020; Power_W: 3W; TempCo: 75 ppm/C; SizeArea_mm2: 20.16; SizeX_mm: 6.3; SizeY_mm: 3.2; SizeZ_mm: 0.71; EIA_Code: E96; U/M: EA; AEC Category: Q200
R304 R314 = CMP-0026404-2: RES, 49.9, 1%, 0.063 W, AEC-Q200 Grade 0, 0402; PartNumber: CRCW040249R9FKED; Manufacturer: Vishay-Dale; Value: 49.9; Value_Code: 49R9; Power_W: 63mW; Value2: 0.063W; VDC_V: 50V; TempCo: 100 ppm/C; EIA_Code: E96; SizeArea_mm2: 0.5; SizeX_mm: 1; SizeZ_mm: 0.6; AEC Category: Q200; AEC Qualified: Y; AEC Grade: 0
TP102 TP103 TP105 TP106 TP300-TP302 TP310 = CMP-0055137-1: Test Point, Miniature, Red, TH; Manufacturer: Keystone; CNHeader: FALSE; ContactFinish: Silver; CT: TRUE; Green_Lifecycle: Active; Green_REACh: Passed
TP107 = CMP-0055139-1: Test Point, Miniature, White, TH; Manufacturer: Keystone; ContactFinish: Silver; Green_Lifecycle: Active; Green_REACh: Passed; CNHeader: FALSE; CT: TRUE
TP109 TP303 TP304 TP307 = CMP-0055138-1: Test Point, Miniature, Black, TH; Manufacturer: Keystone; CNHeader: FALSE; ContactFinish: Silver; CT: TRUE; Green_Lifecycle: Active; Green_REACh: Passed
TP305 TP308 TP309 TP315 = CMP-0055153-1: Test Point, Compact, SMT; Manufacturer: Keystone; Green_Lifecycle: Active; Green_REACh: Passed; CNHeader: FALSE; CT: TRUE
U1 U2 = CMP-0014070-7: 4-16Vin 40A Stackable Synchronous Step-down SWIFT(TM) Converter w/ Adaptive Internal Compensation, RVF0040A (LQFN-CLIP-40); Alternate PartNumber: TPS543C20RVFR; Manufacturer: Texas Instruments; CompType: IC; AEC Category: Q200; AEC Qualified: N; Rating: Catalog; SizeArea_mm2: 35; SizeAreaWB_mm2: 63; SizeX_mm: 5; SizeY_mm: 7; SizeZ_mm: 1.52

## Sheet PMP21619_Caps&Hardware.SchDoc
size 431 x 279 mm; Date: Not shown in title block; ApprovedBy: Not shown in title block; CheckedBy: Not shown in title block; Author: Not shown in title block; CompanyName: Not shown in title block; Engineer: Not shown in title block; Organization: Not shown in title block; Address1: Not shown in title block; Address2: Not shown in title block; Address3: Not shown in title block; Address4: Not shown in title block; DocumentNumber: 1; Revision: Use project parameter SCH_Rev; SheetNumber: 3; SheetTotal: 3; PageSetup: Record=PageOptions¦CenterHorizontal=True¦CenterVertical=True¦PrintScale=1.00¦XCorrection=1.00¦YCorrection=1.00¦PrintKind=0¦BorderSize=5000000¦LeftOffset=0¦BottomOffset=0¦Orientation=2¦PaperLength=1000¦PaperWidth=1000¦Scale=100¦PaperSource=15¦PrintQuality=600¦MediaType=1¦DitherType=10¦PaperKind=Letter¦PrintScaleMode=1
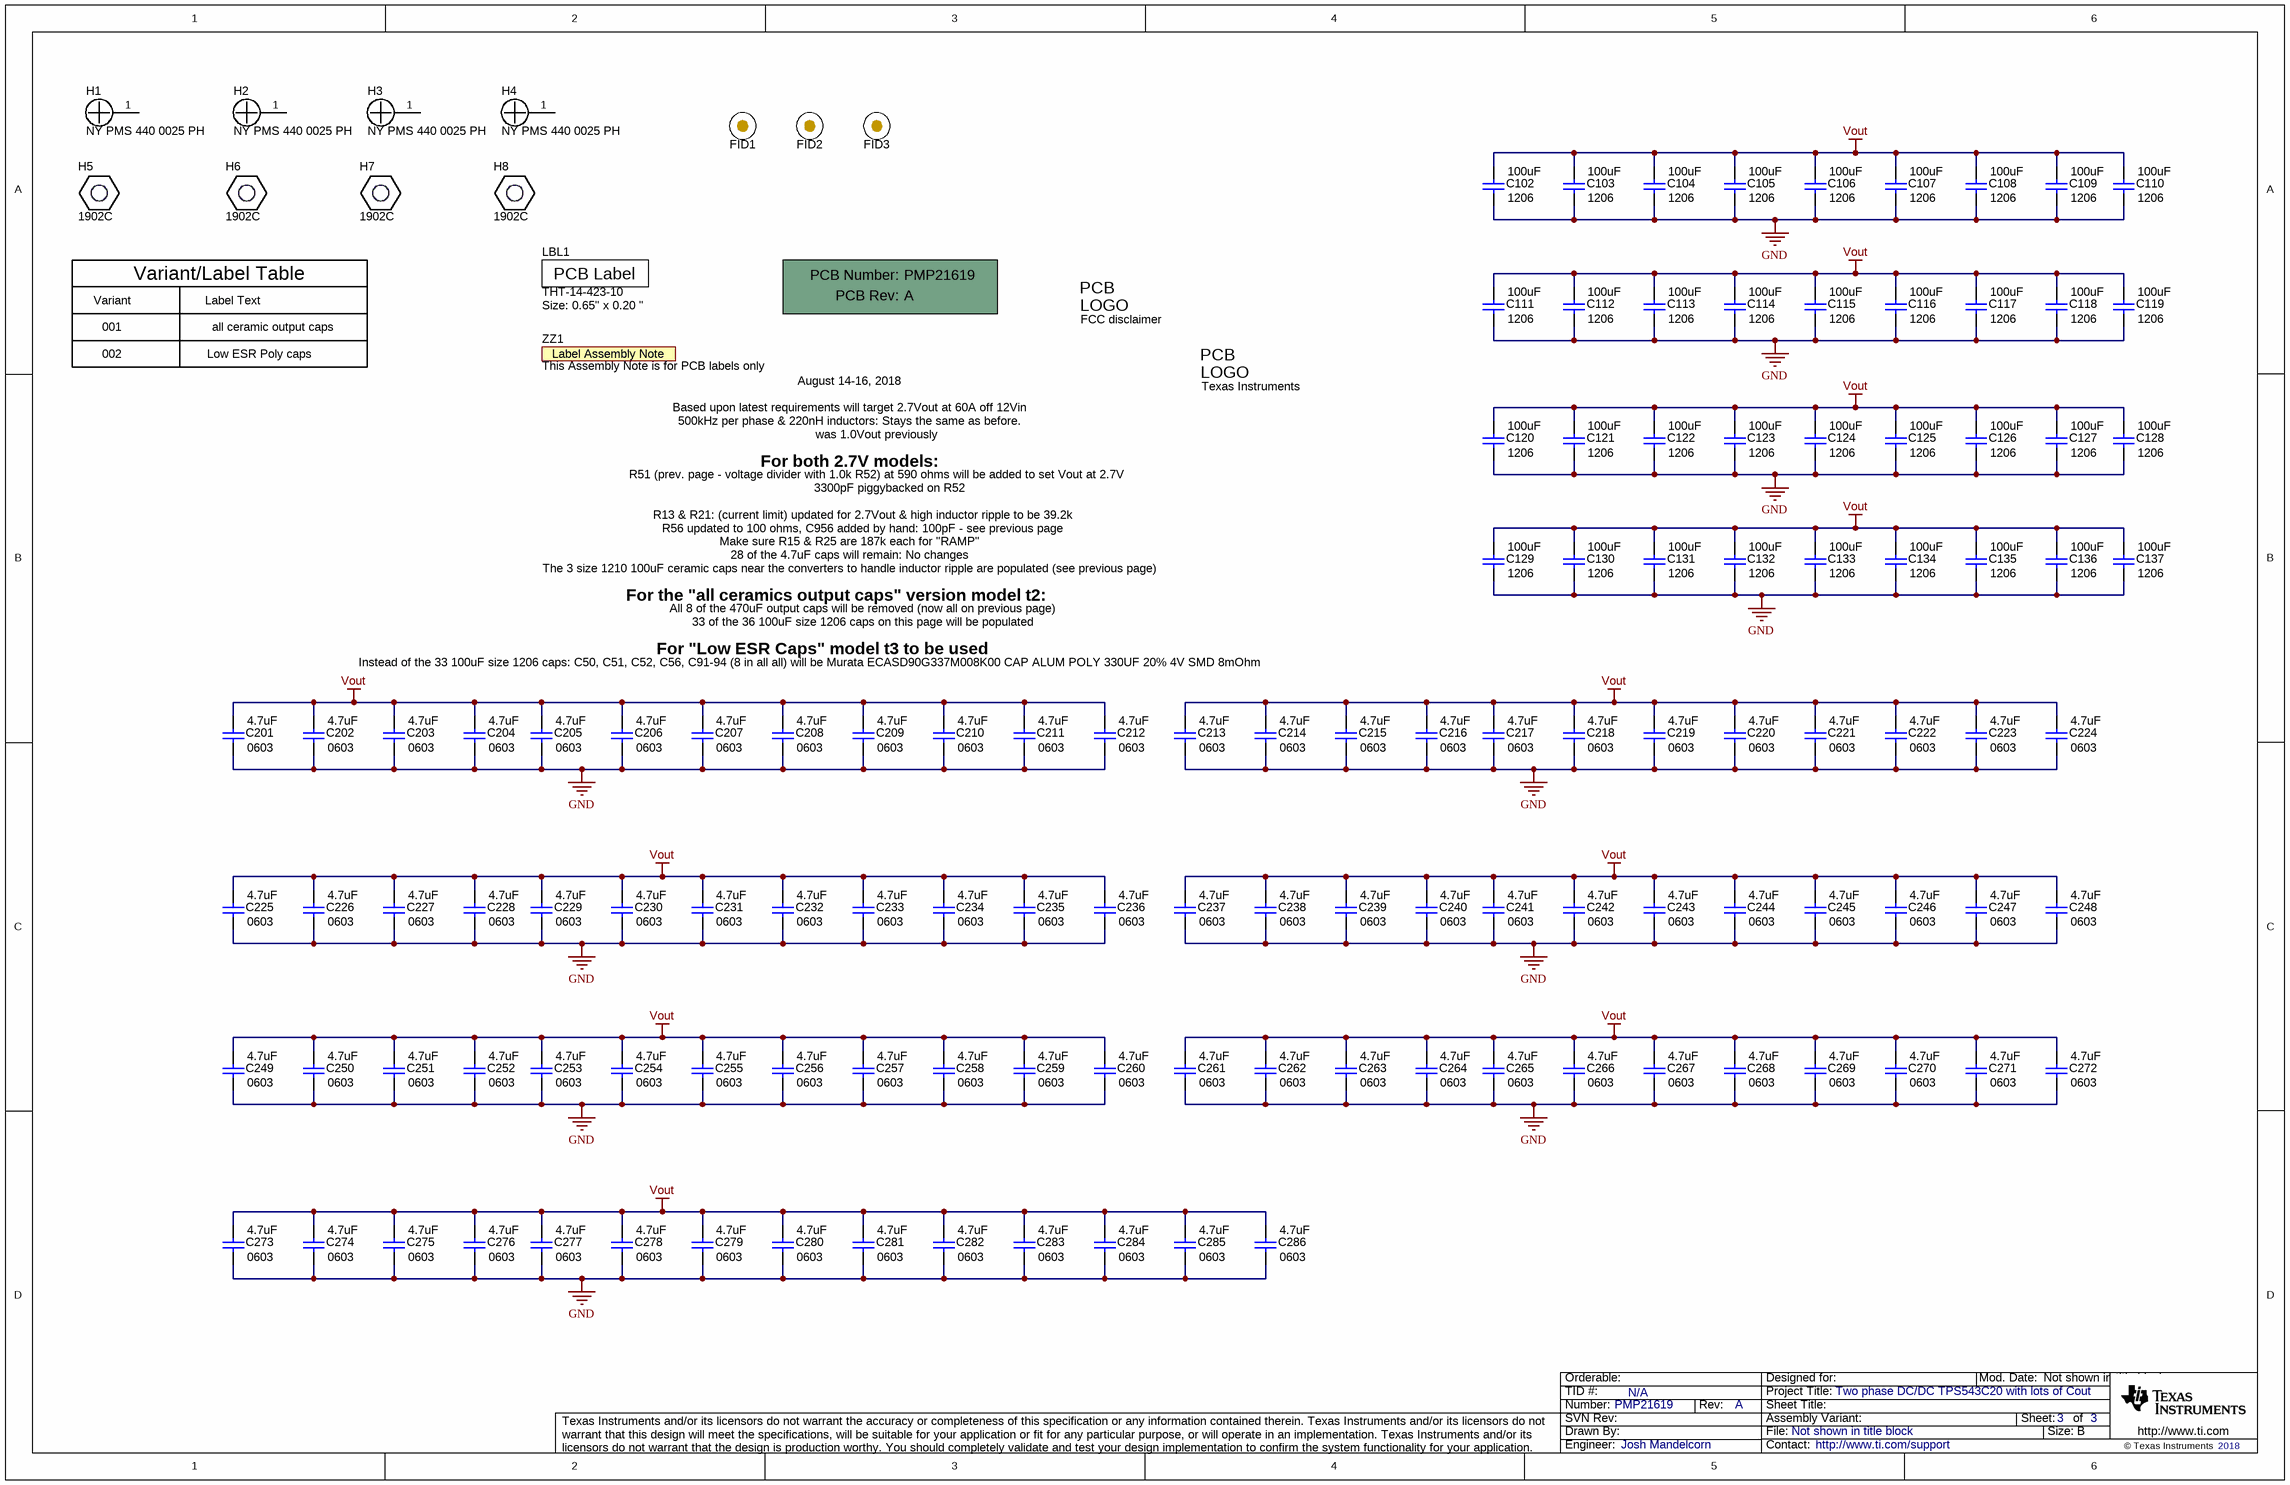
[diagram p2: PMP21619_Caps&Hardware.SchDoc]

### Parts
!PCB  Printed Circuit Board  (value not drawn)  (mechanical)
C102  Cap_Case: 1206  ValueDisplayed: 100uF  [1206_190L]  (hidden comment: C3216X5R0J107M160AB)
C103  Cap_Case: 1206  ValueDisplayed: 100uF  [1206_190L]  (hidden comment: C3216X5R0J107M160AB)
C104  Cap_Case: 1206  ValueDisplayed: 100uF  [1206_190L]  (hidden comment: C3216X5R0J107M160AB)
C105  Cap_Case: 1206  ValueDisplayed: 100uF  [1206_190L]  (hidden comment: C3216X5R0J107M160AB)
C106  Cap_Case: 1206  ValueDisplayed: 100uF  [1206_190L]  (hidden comment: C3216X5R0J107M160AB)
C107  Cap_Case: 1206  ValueDisplayed: 100uF  [1206_190L]  (hidden comment: C3216X5R0J107M160AB)
C108  Cap_Case: 1206  ValueDisplayed: 100uF  [1206_190L]  (hidden comment: C3216X5R0J107M160AB)
C109  Cap_Case: 1206  ValueDisplayed: 100uF  [1206_190L]  (hidden comment: C3216X5R0J107M160AB)
C110  Cap_Case: 1206  ValueDisplayed: 100uF  [1206_190L]  (hidden comment: C3216X5R0J107M160AB)
C111  Cap_Case: 1206  ValueDisplayed: 100uF  [1206_190L]  (hidden comment: C3216X5R0J107M160AB)
C112  Cap_Case: 1206  ValueDisplayed: 100uF  [1206_190L]  (hidden comment: C3216X5R0J107M160AB)
C113  Cap_Case: 1206  ValueDisplayed: 100uF  [1206_190L]  (hidden comment: C3216X5R0J107M160AB)
C114  Cap_Case: 1206  ValueDisplayed: 100uF  [1206_190L]  (hidden comment: C3216X5R0J107M160AB)
C115  Cap_Case: 1206  ValueDisplayed: 100uF  [1206_190L]  (hidden comment: C3216X5R0J107M160AB)
C116  Cap_Case: 1206  ValueDisplayed: 100uF  [1206_190L]  (hidden comment: C3216X5R0J107M160AB)
C117  Cap_Case: 1206  ValueDisplayed: 100uF  [1206_190L]  (hidden comment: C3216X5R0J107M160AB)
C118  Cap_Case: 1206  ValueDisplayed: 100uF  [1206_190L]  (hidden comment: C3216X5R0J107M160AB)
C119  Cap_Case: 1206  ValueDisplayed: 100uF  [1206_190L]  (hidden comment: C3216X5R0J107M160AB)
C120  Cap_Case: 1206  ValueDisplayed: 100uF  [1206_190L]  (hidden comment: C3216X5R0J107M160AB)
C121  Cap_Case: 1206  ValueDisplayed: 100uF  [1206_190L]  (hidden comment: C3216X5R0J107M160AB)
C122  Cap_Case: 1206  ValueDisplayed: 100uF  [1206_190L]  (hidden comment: C3216X5R0J107M160AB)
C123  Cap_Case: 1206  ValueDisplayed: 100uF  [1206_190L]  (hidden comment: C3216X5R0J107M160AB)
C124  Cap_Case: 1206  ValueDisplayed: 100uF  [1206_190L]  (hidden comment: C3216X5R0J107M160AB)
C125  Cap_Case: 1206  ValueDisplayed: 100uF  [1206_190L]  (hidden comment: C3216X5R0J107M160AB)
C126  Cap_Case: 1206  ValueDisplayed: 100uF  [1206_190L]  (hidden comment: C3216X5R0J107M160AB)
C127  Cap_Case: 1206  ValueDisplayed: 100uF  [1206_190L]  (hidden comment: C3216X5R0J107M160AB)
C128  Cap_Case: 1206  ValueDisplayed: 100uF  [1206_190L]  (hidden comment: C3216X5R0J107M160AB)
C129  Cap_Case: 1206  ValueDisplayed: 100uF  [1206_190L]  (hidden comment: C3216X5R0J107M160AB)
C130  Cap_Case: 1206  ValueDisplayed: 100uF  [1206_190L]  (hidden comment: C3216X5R0J107M160AB)
C131  Cap_Case: 1206  ValueDisplayed: 100uF  [1206_190L]  (hidden comment: C3216X5R0J107M160AB)
C132  Cap_Case: 1206  ValueDisplayed: 100uF  [1206_190L]  (hidden comment: C3216X5R0J107M160AB)
C133  Cap_Case: 1206  ValueDisplayed: 100uF  [1206_190L]  (hidden comment: C3216X5R0J107M160AB)
C134  Cap_Case: 1206  ValueDisplayed: 100uF  [1206_190L]  (hidden comment: C3216X5R0J107M160AB)
C135  Cap_Case: 1206  ValueDisplayed: 100uF  [1206_190L]  (hidden comment: C3216X5R0J107M160AB)
C136  Cap_Case: 1206  ValueDisplayed: 100uF  [1206_190L]  (hidden comment: C3216X5R0J107M160AB)
C137  Cap_Case: 1206  ValueDisplayed: 100uF  [1206_190L]  (hidden comment: C3216X5R0J107M160AB)
C201  PackageReference: 0603  ValueDisplayed: 4.7uF  [0603L]  (hidden comment: C1608X6S1C475K080AC)
C202  PackageReference: 0603  ValueDisplayed: 4.7uF  [0603L]  (hidden comment: C1608X6S1C475K080AC)
C203  PackageReference: 0603  ValueDisplayed: 4.7uF  [0603L]  (hidden comment: C1608X6S1C475K080AC)
C204  PackageReference: 0603  ValueDisplayed: 4.7uF  [0603L]  (hidden comment: C1608X6S1C475K080AC)
C205  PackageReference: 0603  ValueDisplayed: 4.7uF  [0603L]  (hidden comment: C1608X6S1C475K080AC)
C206  PackageReference: 0603  ValueDisplayed: 4.7uF  [0603L]  (hidden comment: C1608X6S1C475K080AC)
C207  PackageReference: 0603  ValueDisplayed: 4.7uF  [0603L]  (hidden comment: C1608X6S1C475K080AC)
C208  PackageReference: 0603  ValueDisplayed: 4.7uF  [0603L]  (hidden comment: C1608X6S1C475K080AC)
C209  PackageReference: 0603  ValueDisplayed: 4.7uF  [0603L]  (hidden comment: C1608X6S1C475K080AC)
C210  PackageReference: 0603  ValueDisplayed: 4.7uF  [0603L]  (hidden comment: C1608X6S1C475K080AC)
C211  PackageReference: 0603  ValueDisplayed: 4.7uF  [0603L]  (hidden comment: C1608X6S1C475K080AC)
C212  PackageReference: 0603  ValueDisplayed: 4.7uF  [0603L]  (hidden comment: C1608X6S1C475K080AC)
C213  PackageReference: 0603  ValueDisplayed: 4.7uF  [0603L]  (hidden comment: C1608X6S1C475K080AC)
C214  PackageReference: 0603  ValueDisplayed: 4.7uF  [0603L]  (hidden comment: C1608X6S1C475K080AC)
C215  PackageReference: 0603  ValueDisplayed: 4.7uF  [0603L]  (hidden comment: C1608X6S1C475K080AC)
C216  PackageReference: 0603  ValueDisplayed: 4.7uF  [0603L]  (hidden comment: C1608X6S1C475K080AC)
C217  PackageReference: 0603  ValueDisplayed: 4.7uF  [0603L]  (hidden comment: C1608X6S1C475K080AC)
C218  PackageReference: 0603  ValueDisplayed: 4.7uF  [0603L]  (hidden comment: C1608X6S1C475K080AC)
C219  PackageReference: 0603  ValueDisplayed: 4.7uF  [0603L]  (hidden comment: C1608X6S1C475K080AC)
C220  PackageReference: 0603  ValueDisplayed: 4.7uF  [0603L]  (hidden comment: C1608X6S1C475K080AC)
C221  PackageReference: 0603  ValueDisplayed: 4.7uF  [0603L]  (hidden comment: C1608X6S1C475K080AC)
C222  PackageReference: 0603  ValueDisplayed: 4.7uF  [0603L]  (hidden comment: C1608X6S1C475K080AC)
C223  PackageReference: 0603  ValueDisplayed: 4.7uF  [0603L]  (hidden comment: C1608X6S1C475K080AC)
C224  PackageReference: 0603  ValueDisplayed: 4.7uF  [0603L]  (hidden comment: C1608X6S1C475K080AC)
C225  PackageReference: 0603  ValueDisplayed: 4.7uF  [0603L]  (hidden comment: C1608X6S1C475K080AC)
C226  PackageReference: 0603  ValueDisplayed: 4.7uF  [0603L]  (hidden comment: C1608X6S1C475K080AC)
C227  PackageReference: 0603  ValueDisplayed: 4.7uF  [0603L]  (hidden comment: C1608X6S1C475K080AC)
C228  PackageReference: 0603  ValueDisplayed: 4.7uF  [0603L]  (hidden comment: C1608X6S1C475K080AC)
C229  PackageReference: 0603  ValueDisplayed: 4.7uF  [0603L]  (hidden comment: C1608X6S1C475K080AC)
C230  PackageReference: 0603  ValueDisplayed: 4.7uF  [0603L]  (hidden comment: C1608X6S1C475K080AC)
C231  PackageReference: 0603  ValueDisplayed: 4.7uF  [0603L]  (hidden comment: C1608X6S1C475K080AC)
C232  PackageReference: 0603  ValueDisplayed: 4.7uF  [0603L]  (hidden comment: C1608X6S1C475K080AC)
C233  PackageReference: 0603  ValueDisplayed: 4.7uF  [0603L]  (hidden comment: C1608X6S1C475K080AC)
C234  PackageReference: 0603  ValueDisplayed: 4.7uF  [0603L]  (hidden comment: C1608X6S1C475K080AC)
C235  PackageReference: 0603  ValueDisplayed: 4.7uF  [0603L]  (hidden comment: C1608X6S1C475K080AC)
C236  PackageReference: 0603  ValueDisplayed: 4.7uF  [0603L]  (hidden comment: C1608X6S1C475K080AC)
C237  PackageReference: 0603  ValueDisplayed: 4.7uF  [0603L]  (hidden comment: C1608X6S1C475K080AC)
C238  PackageReference: 0603  ValueDisplayed: 4.7uF  [0603L]  (hidden comment: C1608X6S1C475K080AC)
C239  PackageReference: 0603  ValueDisplayed: 4.7uF  [0603L]  (hidden comment: C1608X6S1C475K080AC)
C240  PackageReference: 0603  ValueDisplayed: 4.7uF  [0603L]  (hidden comment: C1608X6S1C475K080AC)
C241  PackageReference: 0603  ValueDisplayed: 4.7uF  [0603L]  (hidden comment: C1608X6S1C475K080AC)
C242  PackageReference: 0603  ValueDisplayed: 4.7uF  [0603L]  (hidden comment: C1608X6S1C475K080AC)
C243  PackageReference: 0603  ValueDisplayed: 4.7uF  [0603L]  (hidden comment: C1608X6S1C475K080AC)
C244  PackageReference: 0603  ValueDisplayed: 4.7uF  [0603L]  (hidden comment: C1608X6S1C475K080AC)
C245  PackageReference: 0603  ValueDisplayed: 4.7uF  [0603L]  (hidden comment: C1608X6S1C475K080AC)
C246  PackageReference: 0603  ValueDisplayed: 4.7uF  [0603L]  (hidden comment: C1608X6S1C475K080AC)
C247  PackageReference: 0603  ValueDisplayed: 4.7uF  [0603L]  (hidden comment: C1608X6S1C475K080AC)
C248  PackageReference: 0603  ValueDisplayed: 4.7uF  [0603L]  (hidden comment: C1608X6S1C475K080AC)
C249  PackageReference: 0603  ValueDisplayed: 4.7uF  [0603L]  (hidden comment: C1608X6S1C475K080AC)
C250  PackageReference: 0603  ValueDisplayed: 4.7uF  [0603L]  (hidden comment: C1608X6S1C475K080AC)
C251  PackageReference: 0603  ValueDisplayed: 4.7uF  [0603L]  (hidden comment: C1608X6S1C475K080AC)
C252  PackageReference: 0603  ValueDisplayed: 4.7uF  [0603L]  (hidden comment: C1608X6S1C475K080AC)
C253  PackageReference: 0603  ValueDisplayed: 4.7uF  [0603L]  (hidden comment: C1608X6S1C475K080AC)
C254  PackageReference: 0603  ValueDisplayed: 4.7uF  [0603L]  (hidden comment: C1608X6S1C475K080AC)
C255  PackageReference: 0603  ValueDisplayed: 4.7uF  [0603L]  (hidden comment: C1608X6S1C475K080AC)
C256  PackageReference: 0603  ValueDisplayed: 4.7uF  [0603L]  (hidden comment: C1608X6S1C475K080AC)
C257  PackageReference: 0603  ValueDisplayed: 4.7uF  [0603L]  (hidden comment: C1608X6S1C475K080AC)
C258  PackageReference: 0603  ValueDisplayed: 4.7uF  [0603L]  (hidden comment: C1608X6S1C475K080AC)
C259  PackageReference: 0603  ValueDisplayed: 4.7uF  [0603L]  (hidden comment: C1608X6S1C475K080AC)
C260  PackageReference: 0603  ValueDisplayed: 4.7uF  [0603L]  (hidden comment: C1608X6S1C475K080AC)
C261  PackageReference: 0603  ValueDisplayed: 4.7uF  [0603L]  (hidden comment: C1608X6S1C475K080AC)
C262  PackageReference: 0603  ValueDisplayed: 4.7uF  [0603L]  (hidden comment: C1608X6S1C475K080AC)
C263  PackageReference: 0603  ValueDisplayed: 4.7uF  [0603L]  (hidden comment: C1608X6S1C475K080AC)
C264  PackageReference: 0603  ValueDisplayed: 4.7uF  [0603L]  (hidden comment: C1608X6S1C475K080AC)
C265  PackageReference: 0603  ValueDisplayed: 4.7uF  [0603L]  (hidden comment: C1608X6S1C475K080AC)
C266  PackageReference: 0603  ValueDisplayed: 4.7uF  [0603L]  (hidden comment: C1608X6S1C475K080AC)
C267  PackageReference: 0603  ValueDisplayed: 4.7uF  [0603L]  (hidden comment: C1608X6S1C475K080AC)
C268  PackageReference: 0603  ValueDisplayed: 4.7uF  [0603L]  (hidden comment: C1608X6S1C475K080AC)
C269  PackageReference: 0603  ValueDisplayed: 4.7uF  [0603L]  (hidden comment: C1608X6S1C475K080AC)
C270  PackageReference: 0603  ValueDisplayed: 4.7uF  [0603L]  (hidden comment: C1608X6S1C475K080AC)
C271  PackageReference: 0603  ValueDisplayed: 4.7uF  [0603L]  (hidden comment: C1608X6S1C475K080AC)
C272  PackageReference: 0603  ValueDisplayed: 4.7uF  [0603L]  (hidden comment: C1608X6S1C475K080AC)
C273  PackageReference: 0603  ValueDisplayed: 4.7uF  [0603L]  (hidden comment: C1608X6S1C475K080AC)
C274  PackageReference: 0603  ValueDisplayed: 4.7uF  [0603L]  (hidden comment: C1608X6S1C475K080AC)
C275  PackageReference: 0603  ValueDisplayed: 4.7uF  [0603L]  (hidden comment: C1608X6S1C475K080AC)
C276  PackageReference: 0603  ValueDisplayed: 4.7uF  [0603L]  (hidden comment: C1608X6S1C475K080AC)
C277  PackageReference: 0603  ValueDisplayed: 4.7uF  [0603L]  (hidden comment: C1608X6S1C475K080AC)
C278  PackageReference: 0603  ValueDisplayed: 4.7uF  [0603L]  (hidden comment: C1608X6S1C475K080AC)
C279  PackageReference: 0603  ValueDisplayed: 4.7uF  [0603L]  (hidden comment: C1608X6S1C475K080AC)
C280  PackageReference: 0603  ValueDisplayed: 4.7uF  [0603L]  (hidden comment: C1608X6S1C475K080AC)
C281  PackageReference: 0603  ValueDisplayed: 4.7uF  [0603L]  (hidden comment: C1608X6S1C475K080AC)
C282  PackageReference: 0603  ValueDisplayed: 4.7uF  [0603L]  (hidden comment: C1608X6S1C475K080AC)
C283  PackageReference: 0603  ValueDisplayed: 4.7uF  [0603L]  (hidden comment: C1608X6S1C475K080AC)
C284  PackageReference: 0603  ValueDisplayed: 4.7uF  [0603L]  (hidden comment: C1608X6S1C475K080AC)
C285  PackageReference: 0603  ValueDisplayed: 4.7uF  [0603L]  (hidden comment: C1608X6S1C475K080AC)
C286  PackageReference: 0603  ValueDisplayed: 4.7uF  [0603L]  (hidden comment: C1608X6S1C475K080AC)
FID1  Fiducial  [Fiducial10-20]  (value not drawn)
FID2  Fiducial  [Fiducial10-20]  (value not drawn)
FID3  Fiducial  [Fiducial10-20]  (value not drawn)
H1  NY PMS 440 0025 PH  [NY PMS 440 0025 PH]
H2  NY PMS 440 0025 PH  [NY PMS 440 0025 PH]
H3  NY PMS 440 0025 PH  [NY PMS 440 0025 PH]
H4  NY PMS 440 0025 PH  [NY PMS 440 0025 PH]
H5  1902C  [Keystone_1902C]
H6  1902C  [Keystone_1902C]
H7  1902C  [Keystone_1902C]
H8  1902C  [Keystone_1902C]
LBL1  THT-14-423-10  Note: Size: 0.65" x 0.20 "  [Label_650x200]
Logo1  Texas Instruments  [TI_Stacked_Overlay_Small]  (no BOM)
Logo3  FCC disclaimer  [FCC_disclaimer]  (no BOM)
ZZ1  This Assembly Note is for PCB labels only  [AssemblyNoteLabel]  (no BOM)

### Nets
GND: C102.2 C103.2 C104.2 C105.2 C106.2 C107.2 C108.2 C109.2 C110.2 C111.2 C112.2 C113.2 C114.2 C115.2 C116.2 C117.2 C118.2 C119.2 C120.2 C121.2 C122.2 C123.2 C124.2 C125.2 C126.2 C127.2 C128.2 C129.2 C130.2 C131.2 C132.2 C133.2 C134.2 C135.2 C136.2 C137.2 C201.2 C202.2 C203.2 C204.2 C205.2 C206.2 C207.2 C208.2 C209.2 C210.2 C211.2 C212.2 C213.2 C214.2 C215.2 C216.2 C217.2 C218.2 C219.2 C220.2 C221.2 C222.2 C223.2 C224.2 C225.2 C226.2 C227.2 C228.2 C229.2 C230.2 C231.2 C232.2 C233.2 C234.2 C235.2 C236.2 C237.2 C238.2 C239.2 C240.2 C241.2 C242.2 C243.2 C244.2 C245.2 C246.2 C247.2 C248.2 C249.2 C250.2 C251.2 C252.2 C253.2 C254.2 C255.2 C256.2 C257.2 C258.2 C259.2 C260.2 C261.2 C262.2 C263.2 C264.2 C265.2 C266.2 C267.2 C268.2 C269.2 C270.2 C271.2 C272.2 C273.2 C274.2 C275.2 C276.2 C277.2 C278.2 C279.2 C280.2 C281.2 C282.2 C283.2 C284.2 C285.2 C286.2
Vout: C102.1 C103.1 C104.1 C105.1 C106.1 C107.1 C108.1 C109.1 C110.1 C111.1 C112.1 C113.1 C114.1 C115.1 C116.1 C117.1 C118.1 C119.1 C120.1 C121.1 C122.1 C123.1 C124.1 C125.1 C126.1 C127.1 C128.1 C129.1 C130.1 C131.1 C132.1 C133.1 C134.1 C135.1 C136.1 C137.1 C201.1 C202.1 C203.1 C204.1 C205.1 C206.1 C207.1 C208.1 C209.1 C210.1 C211.1 C212.1 C213.1 C214.1 C215.1 C216.1 C217.1 C218.1 C219.1 C220.1 C221.1 C222.1 C223.1 C224.1 C225.1 C226.1 C227.1 C228.1 C229.1 C230.1 C231.1 C232.1 C233.1 C234.1 C235.1 C236.1 C237.1 C238.1 C239.1 C240.1 C241.1 C242.1 C243.1 C244.1 C245.1 C246.1 C247.1 C248.1 C249.1 C250.1 C251.1 C252.1 C253.1 C254.1 C255.1 C256.1 C257.1 C258.1 C259.1 C260.1 C261.1 C262.1 C263.1 C264.1 C265.1 C266.1 C267.1 C268.1 C269.1 C270.1 C271.1 C272.1 C273.1 C274.1 C275.1 C276.1 C277.1 C278.1 C279.1 C280.1 C281.1 C282.1 C283.1 C284.1 C285.1 C286.1

Not connected (* = marked no-connect by the designer): H1 1; H2 1; H3 1; H4 1

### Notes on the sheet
- Variant
- Variant/Label Table
- Label Text
- 001
- 002
- Low ESR Poly caps
- all ceramic output caps
- Based upon latest requirements will target 2.7Vout at 60A off 12Vin
- 500kHz per phase & 220nH inductors: Stays the same as before.
- August 14-16, 2018
- was 1.0Vout previously
- For both 2.7V models:
- R51 (prev. page - voltage divider with 1.0k R52) at 590 ohms will be added to set Vout at 2.7V
- 3300pF piggybacked on R52
- 28 of the 4.7uF caps will remain: No changes
- Make sure R15 & R25 are 187k each for "RAMP"
- The 3 size 1210 100uF ceramic caps near the converters to handle inductor ripple are populated (see previous page)
- R13 & R21: (current limit) updated for 2.7Vout & high inductor ripple to be 39.2k
- R56 updated to 100 ohms, C956 added by hand: 100pF - see previous page
- For the "all ceramics output caps" version model t2:
- All 8 of the 470uF output caps will be removed (now all on previous page)
- 33 of the 36 100uF size 1206 caps on this page will be populated
- Instead of the 33 100uF size 1206 caps: C50, C51, C52, C56, C91-94 (8 in all all) will be Murata ECASD90G337M008K00 CAP ALUM POLY 330UF 20% 4V SMD 8mOhm
- For "Low ESR Caps" model t3 to be used

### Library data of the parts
!PCB = CMP-0003618-2: Manufacturer: Any; PartNumber: PMP21619
C102-C137 = CMP-0064957-2: CAP, CERM, 100 uF, 6.3 V,+/- 20%, X5R, 1206; Manufacturer: TDK; TaMin_C: -55°C; Polarized: N; SizeAreaWB_mm2: 10.92; Value1: Unknown; U/M: EA; Value: 100uF; TaMax_C: 85°C; SizeZ_mm: 1.9; SizeX_mm: 3.2; SizeY_mm: 1.6; Value2: 6.3V; SizeArea_mm2: 5.12; CompType: Capacitor; Cap_F: 100µF; AEC Category: Q200
C201-C286 = CMP-0007028-4: CAP, CERM, 4.7 uF, 16 V, +/- 10%, X6S, 0603; Manufacturer: TDK; TaMin_C: -55°C; ESR_ohm: 3.728m; Polarized: N; SizeAreaWB_mm2: 4.68; Value1: 0.003728 ohm; U/M: EA; Value: 4.7uF; TaMax_C: 105°C; SizeZ_mm: 1; SizeX_mm: 1.6; SizeY_mm: 0.8; Value2: 16V; SizeArea_mm2: 1.28; CompType: Capacitor; Cap_F: 4.7µF; IRMS_A: 2.69359A; AEC Category: Q200
FID1-FID3 = CMP-0077181-1: Fiducial mark.  There is nothing to buy or mount.
H1-H4 = CMP-0003617-1: Machine Screw, Round, #4-40 x 1/4, Nylon, Philips panhead; Manufacturer: B&F Fastener Supply; CompType: Hardware
H5-H8 = CMP-0003610-1: Standoff, Hex, 0.5"L #4-40 Nylon; Manufacturer: Keystone; CompType: Hardware
LBL1 = CMP-0003625-1: Thermal Transfer Printable Labels, 0.650" W x 0.200" H - 10,000 per roll; Manufacturer: Brady; CompType: Label
Logo1 = CMP-0074838-1: Texas Instrument Corporate Signature; SymbolCreator: a0412235; Lib Reference: TI_Logo; Library Reference: Logo
Logo3 = CMP-0074847-1: FCC_disclaimer; Library Reference: Logo
ZZ1 = CMP-0003616-3

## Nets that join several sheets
GND: PMP21619_2phaseDCDC (85 pins), PMP21619_Caps&Hardware (122 pins)
Vout: PMP21619_2phaseDCDC (28 pins), PMP21619_Caps&Hardware (122 pins)

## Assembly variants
001: not fitted FID1 FID2 FID3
